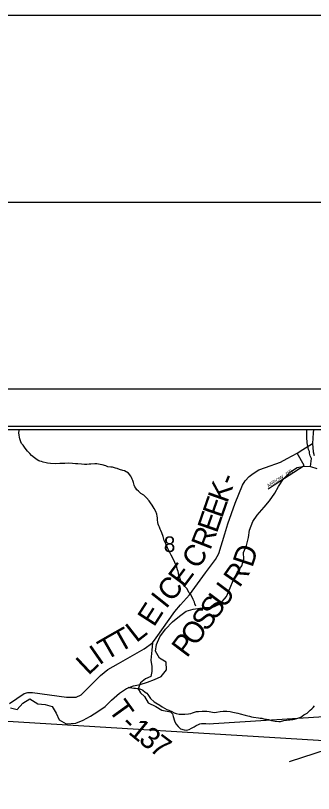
# Model space of a CAD drawing. Extents: x 0 to 34, y 0 to 22.
# Drawn here: x 3.885 to 4.684, y 19.917 to 22 of the extents above; entities that cross this region are included whole.
import ezdxf

# ---------------------------------------------------------------- set-up
doc = ezdxf.new("R2010")
doc.units = 0
for name, color, linetype in [('GM_X_County', 7, 'Continuous'), ('GM_X_County_Road', 7, 'Continuous'), ('GM_X_County_Road_Text', 7, 'Continuous'), ('GM_X_Minor_River', 7, 'Continuous'), ('GM_X_Section', 7, 'Continuous'), ('GM_X_Section_Text', 7, 'Continuous'), ('GM_X_State_Route', 7, 'Continuous'), ('GM_X_Township', 7, 'Continuous'), ('GM_X_Township_Road', 7, 'Continuous'), ('GM_X_Township_Road_Text', 7, 'Continuous'), ('GM_X_Township_ROW', 7, 'Continuous'), ('GM_X_Township_Subdivision', 7, 'Continuous'), ('GM_X_Township_Subdivision_Text', 7, 'Continuous'), ('GM_X_US_Route', 7, 'Continuous'), ('SH_Border', 7, 'Continuous'), ('SH_Cut_Line', 7, 'Continuous'), ('SH_Data', 7, 'Continuous')]:
    doc.layers.add(name, color=color, linetype=linetype)

msp = doc.modelspace()

# ---------------------------------------------------------------- linework, layer by layer
at = {"layer": 'GM_X_County'}
msp.add_lwpolyline([(8.9084, 15.63), (8.9084, 20.8908), (2.1084, 20.8908), (2.1084, 19.9847)], dxfattribs=at)
at = {"layer": 'GM_X_County_Road'}
msp.add_lwpolyline([(3.8683, 20.1578), (3.8878, 20.1708), (3.9074, 20.1838), (3.9171, 20.187), (3.9301, 20.187), (4.0212, 20.174), (4.0473, 20.174), (4.0603, 20.1805), (4.1123, 20.2325), (4.1318, 20.2488), (4.1611, 20.265), (4.2294, 20.3041), (4.2522, 20.3203), (4.262, 20.3333), (4.3123, 20.4041), (4.327, 20.4215), (4.3515, 20.4488), (4.394, 20.507), (4.4212, 20.5435), (4.4304, 20.5593), (4.4462, 20.6121), (4.4544, 20.6383), (4.474, 20.6938), (4.4933, 20.7423), (4.5005, 20.7542), (4.5111, 20.7651), (4.5219, 20.7736), (4.5374, 20.7829), (4.5549, 20.7898), (4.5951, 20.804), (4.6132, 20.8132), (4.64, 20.8278), (4.6549, 20.838), (4.6814, 20.8541)], dxfattribs=at)
at = {"layer": 'GM_X_Minor_River'}
for points in [[(3.8935, 20.882), (3.894, 20.8884), (3.8942, 20.8908)], [(4.3686, 20.4183), (4.366, 20.424), (4.3646, 20.4286), (4.361, 20.4358), (4.3588, 20.442), (4.354, 20.45), (4.3507, 20.4535), (4.347, 20.46), (4.3448, 20.4642), (4.3385, 20.4712), (4.3325, 20.4789), (4.3277, 20.4862), (4.3241, 20.4965), (4.3227, 20.501), (4.3206, 20.5113), (4.3192, 20.5155), (4.3163, 20.5251), (4.3119, 20.535), (4.3072, 20.545), (4.3024, 20.5545), (4.2973, 20.5641), (4.2922, 20.5745), (4.2875, 20.5852), (4.2834, 20.5944), (4.2806, 20.6043), (4.2766, 20.6142), (4.2748, 20.6211), (4.273, 20.6245), (4.2704, 20.6299), (4.2694, 20.6333), (4.2676, 20.6379), (4.2665, 20.6425), (4.2655, 20.649), (4.2652, 20.6547), (4.2645, 20.6596), (4.2635, 20.6642), (4.2606, 20.6714), (4.2565, 20.6795), (4.251, 20.6887), (4.2462, 20.6949), (4.2429, 20.7002), (4.2362, 20.7079), (4.2284, 20.7153), (4.2205, 20.72), (4.2146, 20.7265), (4.2101, 20.73), (4.2075, 20.7346), (4.2045, 20.7381), (4.2031, 20.7423), (4.2013, 20.7492), (4.1992, 20.7549), (4.1973, 20.7587), (4.1959, 20.7629), (4.1941, 20.7664), (4.1874, 20.7744), (4.1765, 20.7803), (4.172, 20.7819), (4.1637, 20.784), (4.1573, 20.7871), (4.1528, 20.7876), (4.1445, 20.79), (4.1399, 20.7904), (4.1324, 20.7917), (4.1264, 20.7941), (4.1173, 20.7965), (4.1113, 20.7978), (4.1026, 20.799), (4.0977, 20.7995), (4.0867, 20.7989), (4.0825, 20.7983), (4.0757, 20.798), (4.0692, 20.7977), (4.0613, 20.7982), (4.0518, 20.7992), (4.0454, 20.7996), (4.0371, 20.8002), (4.0272, 20.8007), (4.017, 20.8005), (4.0136, 20.8006), (4.0034, 20.8004), (3.9928, 20.7998), (3.9784, 20.8), (3.9704, 20.8013), (3.9671, 20.8021), (3.9588, 20.8041), (3.9542, 20.8054), (3.9501, 20.8066), (3.9467, 20.8078), (3.9422, 20.8105), (3.9355, 20.8156), (3.9272, 20.8214), (3.9228, 20.8268), (3.9168, 20.8333), (3.9105, 20.841), (3.9046, 20.8491), (3.9002, 20.8541), (3.8991, 20.8587), (3.8958, 20.8667), (3.8955, 20.8709), (3.8941, 20.8763), (3.8935, 20.882)], [(4.6759, 20.792), (4.6786, 20.814), (4.6753, 20.8209), (4.6742, 20.8247), (4.6735, 20.8281), (4.6729, 20.8323), (4.6707, 20.8377), (4.67, 20.8426), (4.6686, 20.8468), (4.6672, 20.8556), (4.6669, 20.8601), (4.6663, 20.8666), (4.666, 20.8712), (4.6657, 20.8776), (4.6659, 20.8863), (4.6662, 20.8908)], [(4.2603, 20.2978), (4.2626, 20.3152), (4.2718, 20.3357), (4.2871, 20.3561), (4.3053, 20.3758), (4.3243, 20.3917), (4.3425, 20.4045), (4.3607, 20.4098), (4.3911, 20.4142), (4.4123, 20.4149), (4.4335, 20.4247), (4.4503, 20.4444), (4.4602, 20.4671), (4.4686, 20.4868), (4.4793, 20.508), (4.4915, 20.5262), (4.4969, 20.5444), (4.4962, 20.5619), (4.5038, 20.5808), (4.5092, 20.602), (4.5123, 20.6218), (4.5215, 20.6445), (4.533, 20.6619), (4.552, 20.6831), (4.5657, 20.7005), (4.5802, 20.721), (4.5901, 20.7384), (4.6031, 20.7588), (4.6221, 20.7778), (4.6403, 20.7891), (4.6585, 20.7928), (4.6759, 20.792), (4.6933, 20.7866)], [(3.8711, 20.1459), (3.8893, 20.1412), (3.9045, 20.1586), (3.9227, 20.17), (3.9446, 20.1562), (3.9636, 20.1546), (3.9832, 20.1492), (3.9938, 20.1318), (4.0013, 20.1135), (4.0202, 20.1028), (4.0467, 20.105), (4.0656, 20.1125), (4.0861, 20.1238), (4.1051, 20.1359), (4.1249, 20.1495), (4.1424, 20.1661), (4.1636, 20.185), (4.1819, 20.1979), (4.2008, 20.2046), (4.219, 20.2084), (4.2387, 20.2144), (4.257, 20.2219), (4.2752, 20.2302), (4.2896, 20.2476), (4.289, 20.2681), (4.2708, 20.2788), (4.2603, 20.2978)], [(4.1867, 20.2011), (4.1901, 20.2007), (4.1966, 20.199), (4.2015, 20.1986), (4.206, 20.1981), (4.2106, 20.198), (4.2155, 20.1972), (4.2222, 20.1952), (4.2264, 20.1936), (4.2327, 20.1878), (4.2365, 20.1851), (4.2391, 20.1816), (4.2464, 20.1705), (4.2561, 20.162), (4.261, 20.1588), (4.2715, 20.1526), (4.2779, 20.1487), (4.2902, 20.1413), (4.2955, 20.1393), (4.3038, 20.1361), (4.3101, 20.1322), (4.3151, 20.131), (4.3237, 20.1293), (4.3271, 20.1289), (4.334, 20.1291), (4.3389, 20.129), (4.3484, 20.1296), (4.3544, 20.1307), (4.359, 20.1321), (4.3697, 20.1357), (4.3754, 20.1364), (4.3852, 20.137), (4.3886, 20.1373), (4.3981, 20.1371), (4.4038, 20.1359), (4.4087, 20.1347), (4.4132, 20.1339), (4.4193, 20.1334), (4.4238, 20.1341), (4.4337, 20.1358), (4.4417, 20.1372), (4.4515, 20.1366), (4.4606, 20.1357), (4.4674, 20.1345), (4.4813, 20.1312), (4.4874, 20.1296), (4.5002, 20.1259), (4.5081, 20.1247), (4.5119, 20.1235), (4.5179, 20.1218), (4.5228, 20.121), (4.536, 20.1192), (4.5413, 20.1184), (4.5455, 20.1179), (4.5538, 20.1159), (4.5579, 20.1151), (4.5636, 20.1142), (4.5715, 20.1118), (4.581, 20.1101), (4.5912, 20.1096), (4.595, 20.1095), (4.6041, 20.1116), (4.6117, 20.113), (4.6159, 20.1137), (4.62, 20.114), (4.6246, 20.1147), (4.6284, 20.1146), (4.6329, 20.1153), (4.639, 20.1171), (4.6444, 20.1189), (4.6501, 20.1211), (4.6535, 20.1237), (4.6581, 20.1267), (4.6616, 20.1285), (4.6666, 20.1319), (4.6712, 20.1356), (4.675, 20.1393), (4.6796, 20.143), (4.6827, 20.1471), (4.6866, 20.1509)]]:
    msp.add_lwpolyline(points, dxfattribs=at)
at = {"layer": 'GM_X_Section'}
msp.add_line((4.8624, 20.8908), (3.7825, 20.8908), dxfattribs=at)
msp.add_lwpolyline([(3.7825, 20.8908), (3.731, 20.118), (4.8149, 20.0525), (4.8624, 20.8908)], dxfattribs=at)
msp.add_lwpolyline([(4.8149, 20.0525), (4.754, 19.0266), (3.6625, 19.0898), (3.731, 20.118)], close=True, dxfattribs=at)
at = {"layer": 'GM_X_State_Route'}
msp.add_lwpolyline([(4.6836, 20.8908), (4.6826, 20.882), (4.6814, 20.8541), (4.6833, 20.8314), (4.6859, 20.8219)], dxfattribs=at)
at = {"layer": 'GM_X_Township'}
msp.add_lwpolyline([(5.9855, 20.8908), (2.1084, 20.8908), (2.1084, 19.9847)], dxfattribs=at)
at = {"layer": 'GM_X_Township_Road'}
msp.add_lwpolyline([(4.2522, 20.3203), (4.2504, 20.3002), (4.2471, 20.2733), (4.2504, 20.2566), (4.2504, 20.2432), (4.2471, 20.2298), (4.2336, 20.2231), (4.2202, 20.213), (4.2135, 20.1963), (4.2202, 20.1862), (4.2303, 20.1762), (4.2403, 20.1594), (4.2605, 20.1494), (4.2772, 20.1393), (4.3002, 20.1353), (4.3053, 20.1302), (4.3077, 20.1229), (4.3113, 20.1106), (4.3147, 20.1026), (4.3208, 20.096), (4.3275, 20.0895), (4.3374, 20.0868)], dxfattribs=at)
at = {"layer": 'GM_X_Township_ROW'}
msp.add_lwpolyline([(4.3374, 20.0868), (4.3438, 20.0864), (4.3505, 20.0876), (4.357, 20.091), (4.3636, 20.0946), (4.3691, 20.0989), (4.3755, 20.1016), (4.3793, 20.1028), (4.3834, 20.104), (4.3876, 20.1043), (4.3948, 20.1043), (4.4038, 20.1031), (4.4154, 20.1035), (4.713, 20.1226), (4.7297, 20.1259), (4.7398, 20.1192), (4.743, 20.1192)], dxfattribs=at)
at = {"layer": 'GM_X_Township_Subdivision'}
for points in [[(4.5782, 20.7428), (4.5786, 20.743), (4.6592, 20.795), (4.64, 20.8278)], [(4.5621, 20.7323), (4.5782, 20.7428)]]:
    msp.add_lwpolyline(points, dxfattribs=at)
at = {"layer": 'GM_X_US_Route'}
msp.add_lwpolyline([(7.1693, 20.827), (4.6185, 20.0016)], dxfattribs=at)
at = {"layer": 'SH_Border'}
msp.add_lwpolyline([(1.5, 21.5), (33.5, 21.5), (33.5, 0.5), (1.5, 0.5)], close=True, dxfattribs=at)
at = {"layer": 'SH_Cut_Line'}
msp.add_lwpolyline([(0, 0), (34, 0), (34, 22), (0, 22)], close=True, dxfattribs=at)
at = {"layer": 'SH_Data'}
for p, q in [((2, 21), (9, 21)), ((2.1, 20.9), (8.9, 20.9))]:
    msp.add_line(p, q, dxfattribs=at)

# ---------------------------------------------------------------- texts
at = {"layer": 'GM_X_County_Road_Text'}
for s, rotation, p in [('K', 70.5167, (4.4525, 20.6919)), ('-', 67.3636, (4.4688, 20.7383)), ('E', 70.7719, (4.4385, 20.6518)), ('E', 70.8018, (4.4245, 20.6117)), ('R', 68.7527, (4.4068, 20.5661)), ('C', 54.1302, (4.3719, 20.5144)), ('D', 71.6329, (4.5198, 20.5197)), ('E', 53.2291, (4.3356, 20.4655)), ('R', 55.1087, (4.4851, 20.4655)), ('C', 49.2435, (4.3024, 20.4268)), ('U', 53.1547, (4.4435, 20.4097)), ('I', 51.5328, (4.2883, 20.4089)), ('S', 53.0549, (4.4204, 20.379)), ('E', 57.223, (4.2559, 20.3603)), ('S', 53.0312, (4.3973, 20.3483)), ('O', 53.0349, (4.3673, 20.3084)), ('T', 29.4911, (4.1639, 20.2926)), ('L', 38.1674, (4.2087, 20.3188)), ('T', 29.9103, (4.1271, 20.2715)), ('P', 53.0357, (4.3442, 20.2778)), ('I', 34.993, (4.1091, 20.2588)), ('L', 43.3183, (4.0799, 20.2311))]:
    msp.add_text(s, height=0.0568, rotation=rotation, dxfattribs=at).set_placement(p)
at = {"layer": 'GM_X_Section_Text'}
msp.add_text('8', height=0.0419, rotation=0, dxfattribs=at).set_placement((4.2823, 20.5631))
at = {"layer": 'GM_X_Township_Road_Text'}
for s, rotation, p in [('T', 305.8081, (4.1318, 20.1412)), ('-', 315.3172, (4.1633, 20.099)), ('1', 320.7415, (4.1843, 20.0786)), ('3', 321.3518, (4.2119, 20.0561)), ('7', 323.0415, (4.2407, 20.0331))]:
    msp.add_text(s, height=0.0568, rotation=rotation, dxfattribs=at).set_placement(p)
at = {"layer": 'GM_X_Township_Subdivision_Text'}
for s, rotation, p in [('DR', 34.5097, (4.6134, 20.767)), ('ARROW', 32.4696, (4.5626, 20.7354))]:
    msp.add_text(s, height=0.00947, rotation=rotation, dxfattribs=at).set_placement(p)

doc.saveas('drawing.dxf')
